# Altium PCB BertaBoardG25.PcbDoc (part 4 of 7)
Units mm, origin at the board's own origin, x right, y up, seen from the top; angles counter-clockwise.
Board outline 160 x 160 mm, 4 copper layers (Top, GND Plane, Power Plane, Bottom), stack 1.344 mm thick; 17 components, 112 nets, 2311 pads, 138 vias.
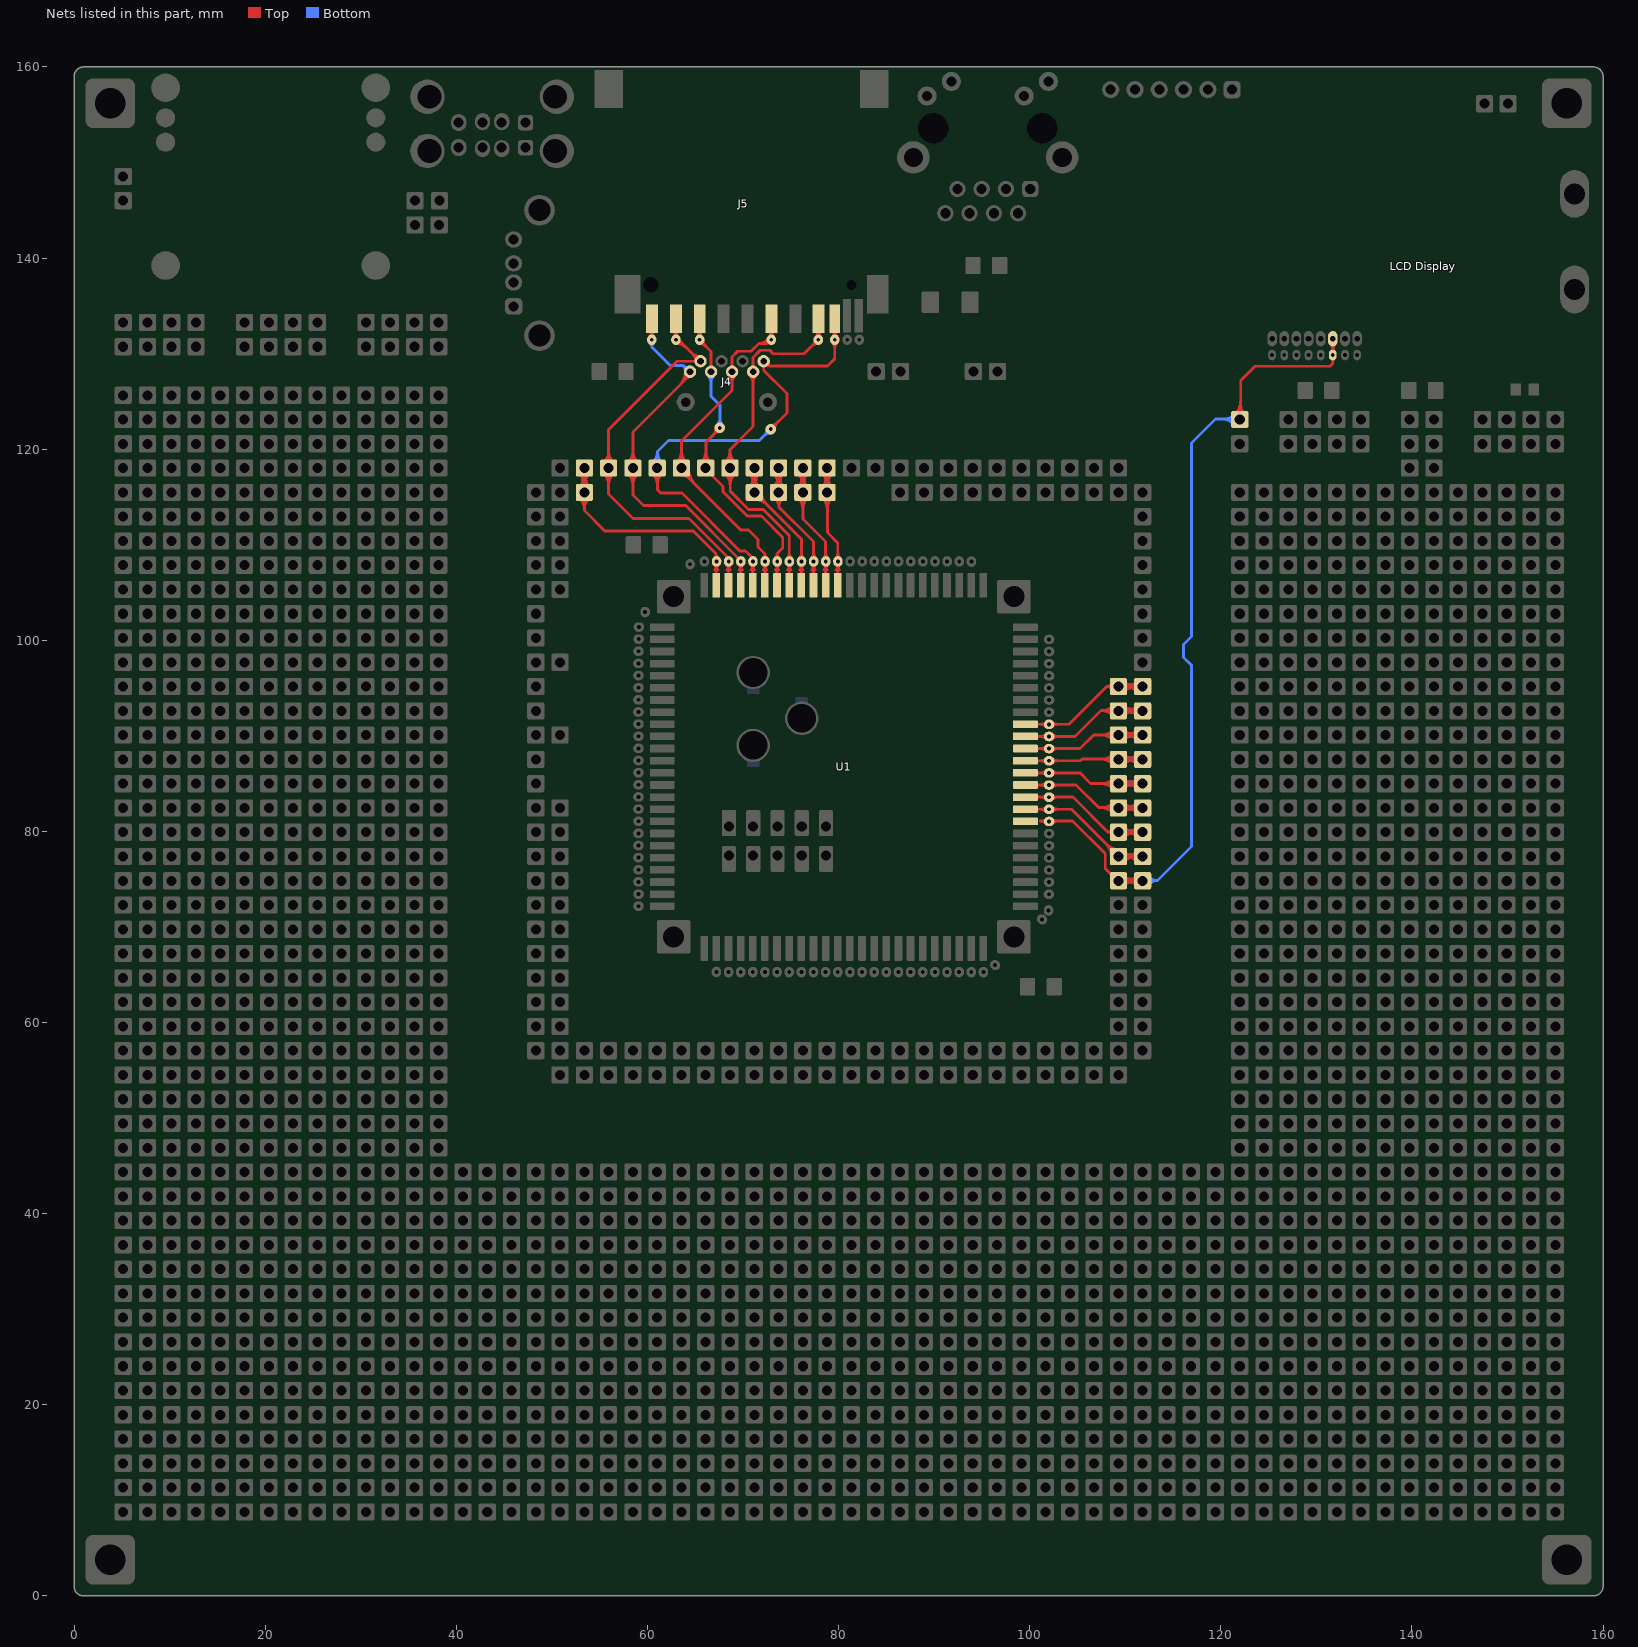
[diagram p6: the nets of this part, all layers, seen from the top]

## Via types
v1: diameter 1.5, hole 0.7, Top to Bottom, tented both sides, 54 vias
v2: diameter 1.1, hole 0.4, Top to Bottom, tented both sides, 49 vias
v3: diameter 1.9, hole 1.05, Top to Bottom, tented both sides, 17 vias
v4: diameter 1.9, hole 1.05, Top to Bottom, 16 vias
v5: diameter 0.9, hole 0.4, Top to Bottom, tented both sides, 2 vias

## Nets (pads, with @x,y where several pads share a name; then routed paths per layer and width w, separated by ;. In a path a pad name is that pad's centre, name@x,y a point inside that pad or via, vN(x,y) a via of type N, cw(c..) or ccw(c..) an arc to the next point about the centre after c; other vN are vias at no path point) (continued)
PA11: pad.0@78.802,115.48 pad.0@78.802,118.02 pad.0@79.934,108.261 U1.S12 | length 49.5
  Top w0.3: pad.0@78.271,114.949 cw(c76.92,113.598) 78.831,113.598 ; pad.0@78.271,116.01 ccw(c76.92,117.361) pad.0@78.831,117.361 ; pad.0@78.271,117.489 cw(c76.92,116.138) pad.0@78.831,116.138 ; pad.0@78.409,116.118 ccw(c78.105,116.611) 78.664,116.761 ccw(c79.626,117.019) pad.0@79.156,116.141 ; pad.0@78.434,116.134 ccw(c77.873,117.133) 78.98,116.836 ccw(c79.661,116.654) pad.0@79.245,116.085 ; pad.0@78.484,115.161 cw(c77.644,114.322) 78.831,114.322 ; pad.0@78.484,115.798 ccw(c77.644,116.637) 78.831,116.637 ; pad.0@78.484,117.701 cw(c77.644,116.862) 78.831,116.862 ; 78.831,113.74 cw(c80.541,113.74) pad.0@79.332,114.949 ; 78.831,114.464 cw(c79.817,114.464) pad.0@79.12,115.161 ; pad.0@78.831,116.28 cw(c80.541,116.28) pad.0@79.332,117.489 ; 78.831,116.495 ccw(c79.817,116.495) pad.0@79.12,115.798 ; 78.831,117.004 cw(c79.817,117.004) pad.0@79.12,117.701 ; pad.0@78.831,117.219 ccw(c80.541,117.219) pad.0@79.332,116.01 ; pad.0@78.831,118.06 78.831,111.269 79.916,110.184 U1.S12@79.916,105.77 ; 78.867,116.413 ccw(c79.383,116.274) pad.0@79.067,115.843 ; pad.0@79.686,107.963 cw(c79.131,107.408) 79.916,107.408 ; pad.0@79.686,108.558 ccw(c79.131,109.114) 79.916,109.114 ; 79.739,107.347 ccw(c79.313,107.773) 79.916,107.773 ccw(c80.52,107.773) 80.093,107.347 ; 79.916,107.324 cw(c80.821,107.324) pad.0@80.181,107.963 ; 79.916,109.198 ccw(c80.821,109.198) pad.0@80.181,108.558
  Bottom w0.3: pad.0@78.271,116.01 ccw(c76.92,117.361) pad.0@78.831,117.361 ; pad.0@78.271,117.489 cw(c76.92,116.138) pad.0@78.831,116.138 ; pad.0@78.409,116.118 ccw(c78.105,116.611) 78.664,116.761 ccw(c79.626,117.019) pad.0@79.156,116.141 ; pad.0@78.434,116.134 ccw(c77.873,117.133) 78.98,116.836 ccw(c79.661,116.654) pad.0@79.245,116.085 ; pad.0@78.484,115.798 ccw(c77.644,116.637) 78.831,116.637 ; pad.0@78.484,117.701 cw(c77.644,116.862) 78.831,116.862 ; pad.0@78.831,115.52 pad.0@78.831,118.06 ; pad.0@78.831,116.28 cw(c80.541,116.28) pad.0@79.332,117.489 ; 78.831,116.495 ccw(c79.817,116.495) pad.0@79.12,115.798 ; 78.831,117.004 cw(c79.817,117.004) pad.0@79.12,117.701 ; pad.0@78.831,117.219 ccw(c80.541,117.219) pad.0@79.332,116.01 ; 78.867,116.413 ccw(c79.383,116.274) pad.0@79.067,115.843
PA12: pad.0@76.262,115.48 pad.0@76.262,118.02 pad.0@78.664,108.261 U1.S11 | length 50.1
  Top w0.3: pad.0@75.731,114.949 cw(c74.38,113.598) 76.291,113.598 ; pad.0@75.731,116.01 ccw(c74.38,117.361) pad.0@76.291,117.361 ; pad.0@75.731,117.489 cw(c74.38,116.138) pad.0@76.291,116.138 ; pad.0@75.869,116.118 ccw(c75.565,116.611) 76.124,116.761 ccw(c77.086,117.019) pad.0@76.616,116.141 ; pad.0@75.894,116.134 ccw(c75.333,117.133) 76.44,116.836 ccw(c77.121,116.654) pad.0@76.705,116.085 ; pad.0@75.944,115.161 cw(c75.104,114.322) 76.291,114.322 ; pad.0@75.944,115.798 ccw(c75.104,116.637) 76.291,116.637 ; pad.0@75.944,117.701 cw(c75.104,116.862) 76.291,116.862 ; 76.291,113.74 cw(c78.001,113.74) pad.0@76.792,114.949 ; 76.291,114.464 cw(c77.277,114.464) pad.0@76.58,115.161 ; pad.0@76.291,116.28 cw(c78.001,116.28) pad.0@76.792,117.489 ; 76.291,116.495 ccw(c77.277,116.495) pad.0@76.58,115.798 ; 76.291,117.004 cw(c77.277,117.004) pad.0@76.58,117.701 ; pad.0@76.291,117.219 ccw(c78.001,117.219) pad.0@76.792,116.01 ; pad.0@76.291,118.06 76.291,112.709 78.646,110.354 U1.S11@78.646,105.77 ; 76.327,116.413 ccw(c76.843,116.274) pad.0@76.527,115.843 ; pad.0@78.416,107.963 cw(c77.861,107.408) 78.646,107.408 ; pad.0@78.416,108.558 ccw(c77.861,109.114) 78.646,109.114 ; 78.469,107.347 ccw(c78.043,107.773) 78.646,107.773 ccw(c79.25,107.773) 78.823,107.347 ; 78.646,107.324 cw(c79.551,107.324) pad.0@78.911,107.963 ; 78.646,109.198 ccw(c79.551,109.198) pad.0@78.911,108.558
  Bottom w0.3: pad.0@75.731,116.01 ccw(c74.38,117.361) pad.0@76.291,117.361 ; pad.0@75.731,117.489 cw(c74.38,116.138) pad.0@76.291,116.138 ; pad.0@75.869,116.118 ccw(c75.565,116.611) 76.124,116.761 ccw(c77.086,117.019) pad.0@76.616,116.141 ; pad.0@75.894,116.134 ccw(c75.333,117.133) 76.44,116.836 ccw(c77.121,116.654) pad.0@76.705,116.085 ; pad.0@75.944,115.798 ccw(c75.104,116.637) 76.291,116.637 ; pad.0@75.944,117.701 cw(c75.104,116.862) 76.291,116.862 ; pad.0@76.291,115.52 pad.0@76.291,118.06 ; pad.0@76.291,116.28 cw(c78.001,116.28) pad.0@76.792,117.489 ; 76.291,116.495 ccw(c77.277,116.495) pad.0@76.58,115.798 ; 76.291,117.004 cw(c77.277,117.004) pad.0@76.58,117.701 ; pad.0@76.291,117.219 ccw(c78.001,117.219) pad.0@76.792,116.01 ; 76.327,116.413 ccw(c76.843,116.274) pad.0@76.527,115.843
PA13: pad.0@73.722,115.48 pad.0@73.722,118.02 pad.0@77.394,108.261 U1.S10 | length 45
  Top w0.3: pad.0@73.191,116.01 ccw(c71.719,117.482) pad.0@73.801,117.482 ; pad.0@73.191,117.489 cw(c71.719,116.017) pad.0@73.801,116.017 ; pad.0@73.281,114.873 cw(c72.609,113.949) 73.751,113.949 ; pad.0@73.376,116.145 ccw(c73.154,116.572) 73.619,116.697 ccw(c74.46,116.922) pad.0@74.063,116.147 ; pad.0@73.404,115.798 ccw(c72.444,116.758) 73.801,116.758 ; pad.0@73.404,117.701 cw(c72.444,116.741) 73.801,116.741 ; pad.0@73.457,115.116 cw(c73.037,114.538) 73.751,114.538 ; pad.0@73.751,115.49 73.751,113.949 ; pad.0@73.801,115.42 pad.0@73.801,117.99 ; 73.801,116.401 cw(c75.341,116.401) pad.0@74.252,117.489 ; 73.801,117.099 ccw(c75.341,117.099) pad.0@74.252,116.01 ; pad.0@74.2,114.902 ccw(c74.987,113.949) 73.751,113.949 ; pad.0@77.146,107.963 cw(c76.591,107.408) 77.376,107.408 ; pad.0@77.146,108.558 ccw(c76.591,109.114) 77.376,109.114 ; 77.199,107.347 ccw(c76.773,107.773) 77.376,107.773 ccw(c77.98,107.773) 77.553,107.347 ; U1.S10@77.376,105.77 77.376,110.324 73.751,113.949 ; 77.376,107.324 cw(c78.281,107.324) pad.0@77.641,107.963 ; 77.376,109.198 ccw(c78.281,109.198) pad.0@77.641,108.558
  Bottom w0.3: pad.0@73.191,116.01 ccw(c71.84,117.361) pad.0@73.751,117.361 ; pad.0@73.191,117.489 cw(c71.84,116.138) pad.0@73.751,116.138 ; pad.0@73.329,116.118 ccw(c73.025,116.611) 73.584,116.761 ccw(c74.546,117.019) pad.0@74.076,116.141 ; pad.0@73.354,116.134 ccw(c72.793,117.133) 73.9,116.836 ccw(c74.581,116.654) pad.0@74.165,116.085 ; pad.0@73.404,115.798 ccw(c72.564,116.637) 73.751,116.637 ; pad.0@73.404,117.701 cw(c72.564,116.862) 73.751,116.862 ; pad.0@73.751,115.52 pad.0@73.751,118.06 ; pad.0@73.751,116.28 cw(c75.461,116.28) pad.0@74.252,117.489 ; 73.751,116.495 ccw(c74.737,116.495) pad.0@74.04,115.798 ; 73.751,117.004 cw(c74.737,117.004) pad.0@74.04,117.701 ; pad.0@73.751,117.219 ccw(c75.461,117.219) pad.0@74.252,116.01 ; 73.787,116.413 ccw(c74.303,116.274) pad.0@73.987,115.843
PA14: pad.0@71.182,115.48 pad.0@71.182,118.02 pad.0@76.124,108.261 U1.S9 | length 51.1
  Top w0.3: pad.0@70.651,116.01 ccw(c69.3,117.361) pad.0@71.211,117.361 ; pad.0@70.651,117.489 cw(c69.3,116.138) pad.0@71.211,116.138 ; pad.0@70.789,116.118 ccw(c70.485,116.611) 71.044,116.761 ccw(c72.006,117.019) pad.0@71.536,116.141 ; pad.0@70.814,116.134 ccw(c70.253,117.133) 71.36,116.836 ccw(c72.041,116.654) pad.0@71.625,116.085 ; pad.0@70.864,115.798 ccw(c70.024,116.637) 71.211,116.637 ; pad.0@70.864,117.701 cw(c70.024,116.862) 71.211,116.862 ; pad.0@71.182,114.73 cw(c71.182,112.775) 72.564,114.157 ; pad.0@71.182,115.03 cw(c71.182,113.799) pad.0@72.052,114.669 ; pad.0@71.211,115.289 71.432,115.289 76.106,110.615 U1.S9@76.106,105.77 ; pad.0@71.211,115.49 pad.0@71.211,118.06 ; pad.0@71.211,116.28 cw(c72.921,116.28) pad.0@71.712,117.489 ; 71.211,116.495 ccw(c72.197,116.495) pad.0@71.5,115.798 ; 71.211,117.004 cw(c72.197,117.004) pad.0@71.5,117.701 ; pad.0@71.211,117.219 ccw(c72.921,117.219) pad.0@71.712,116.01 ; 71.247,116.413 ccw(c71.763,116.274) pad.0@71.447,115.843 ; pad.0@71.632,115.48 ccw(c72.574,115.48) pad.0@71.908,114.813 ; pad.0@71.932,115.48 ccw(c73.599,115.48) 72.42,114.301 ; pad.0@75.876,107.963 cw(c75.321,107.408) 76.106,107.408 ; pad.0@75.876,108.558 ccw(c75.321,109.114) 76.106,109.114 ; 75.929,107.347 ccw(c75.503,107.773) 76.106,107.773 ccw(c76.71,107.773) 76.283,107.347 ; 76.106,107.324 cw(c77.011,107.324) pad.0@76.371,107.963 ; 76.106,109.198 ccw(c77.011,109.198) pad.0@76.371,108.558
  Bottom w0.3: pad.0@70.651,116.01 ccw(c69.3,117.361) pad.0@71.211,117.361 ; pad.0@70.651,117.489 cw(c69.3,116.138) pad.0@71.211,116.138 ; pad.0@70.789,116.118 ccw(c70.485,116.611) 71.044,116.761 ccw(c72.006,117.019) pad.0@71.536,116.141 ; pad.0@70.814,116.134 ccw(c70.253,117.133) 71.36,116.836 ccw(c72.041,116.654) pad.0@71.625,116.085 ; pad.0@70.864,115.798 ccw(c70.024,116.637) 71.211,116.637 ; pad.0@70.864,117.701 cw(c70.024,116.862) 71.211,116.862 ; pad.0@71.211,115.52 pad.0@71.211,118.06 ; pad.0@71.211,116.28 cw(c72.921,116.28) pad.0@71.712,117.489 ; 71.211,116.495 ccw(c72.197,116.495) pad.0@71.5,115.798 ; 71.211,117.004 cw(c72.197,117.004) pad.0@71.5,117.701 ; pad.0@71.211,117.219 ccw(c72.921,117.219) pad.0@71.712,116.01 ; 71.247,116.413 ccw(c71.763,116.274) pad.0@71.447,115.843
PA15: J4.7 J5.7 pad.0@68.642,118.02 pad.0@74.854,108.261 pad.0@77.884,131.451 U1.S8 | length 57.5
  Top w0.3: pad.0@68.111,117.489 cw(c66.76,116.138) 68.671,116.138 ; pad.0@68.111,118.55 ccw(c66.832,119.829) 68.641,119.829 ; pad.0@68.324,117.701 cw(c67.484,116.862) 68.671,116.862 ; pad.0@68.324,118.338 ccw(c67.557,119.105) 68.641,119.105 ; pad.0@68.641,117.9 68.641,119.94 71.058,122.358 J4.7@71.058,128.103 71.058,129.597 71.811,130.35 72.8,130.35 73.17,129.98 76.391,129.98 pad.0@77.901,131.489 ; 68.641,119.107 ccw(c69.73,119.107) pad.0@68.96,118.338 ; 68.641,119.832 ccw(c70.454,119.832) pad.0@69.172,118.55 ; 68.671,116.28 cw(c70.381,116.28) pad.0@69.172,117.489 ; 68.671,117.004 cw(c69.657,117.004) pad.0@68.96,117.701 ; pad.0@68.671,118.03 68.671,115.602 70.574,113.7 72.121,113.7 74.836,110.985 U1.S8@74.836,105.77 ; J4.7@70.705,127.75 cw(c69.851,126.896) 71.058,126.896 cw(c72.266,126.896) J4.7@71.412,127.75 ; pad.0@74.606,107.963 cw(c74.051,107.408) 74.836,107.408 ; pad.0@74.606,108.558 ccw(c74.051,109.114) 74.836,109.114 ; 74.659,107.347 ccw(c74.233,107.773) 74.836,107.773 ccw(c75.44,107.773) 75.013,107.347 ; 74.836,107.324 cw(c75.741,107.324) pad.0@75.101,107.963 ; 74.836,109.198 ccw(c75.741,109.198) pad.0@75.101,108.558 ; 77.165,130.753 cw(c77.884,130.034) pad.0@77.884,131.051 ; 77.336,130.925 ccw(c76.86,131.401) pad.0@77.534,131.401
  Top w0.35: J5.7@77.584,132.46 cw(c76.82,131.695) pad.0@77.901,131.695 ; pad.0@77.654,131.731 ccw(c77.058,132.327) J5.7@77.901,132.327 ; J5.7@77.712,132.37 cw(c77.614,132.158) 77.839,132.098 cw(c78.219,131.996) J5.7@78.071,132.361 ; J5.7@77.72,132.366 cw(c77.565,132.015) 77.935,132.115 cw(c78.131,132.167) J5.7@78.06,132.356 ; pad.0@77.901,131.489 J5.7@77.901,132.4 ; pad.0@77.901,131.688 cw(c78.992,131.688) J5.7@78.22,132.46 ; J5.7@77.901,132.244 ccw(c78.627,132.244) pad.0@78.113,131.731
PA16: J4.3 J5.2@65.477,133.653 pad.0@65.464,131.451 pad.0@66.102,118.02 pad.0@73.584,108.261 U1.S7 | length 52.1
  Top w0.3: J5.2@65.141,132.442 cw(c64.33,131.631) 65.477,131.631 cw(c66.624,131.631) J5.2@65.813,132.442 ; pad.0@65.216,131.748 ccw(c64.586,132.379) J5.2@65.477,132.379 ; J5.2@65.29,132.341 cw(c65.211,132.158) 65.404,132.106 cw(c65.704,132.025) J5.2@65.614,132.323 ; J5.2@65.33,132.326 cw(c65.236,132.036) 65.53,132.115 cw(c65.706,132.162) J5.2@65.642,132.332 ; pad.0@65.464,131.051 cw(c65.464,130.142) 66.106,130.785 ; J5.2@65.477,132.313 ccw(c66.276,132.313) pad.0@65.711,131.748 ; J5.2@65.477,133.653 65.477,131.414 66.658,130.232 J4.3@66.658,128.603 ; pad.0@65.571,118.55 ccw(c64.22,119.901) 66.131,119.901 ; pad.0@65.784,118.338 ccw(c64.944,119.177) 66.131,119.177 ; pad.0@65.814,131.401 ccw(c66.595,131.401) 66.042,130.848 ; pad.0@66.131,117.869 67.901,116.1 67.901,115.539 70.439,113 71.921,113 74.161,110.76 74.161,109.66 73.566,109.065 ; pad.0@66.131,118.03 66.131,120.73 v2@67.601,122.2 ; 66.131,119.035 ccw(c67.117,119.035) pad.0@66.42,118.338 ; 66.131,119.759 ccw(c67.841,119.759) pad.0@66.632,118.55 ; 66.857,121.457 ccw(c66.089,122.225) v2@67.176,122.225 ; 66.978,121.577 cw(c67.576,120.98) v2@67.576,121.825 ; pad.0@73.336,107.963 cw(c72.781,107.408) 73.566,107.408 ; pad.0@73.348,108.569 ccw(c72.896,109.065) 73.566,109.065 ; 73.389,107.347 ccw(c72.963,107.773) 73.566,107.773 ccw(c74.17,107.773) 73.743,107.347 ; U1.S7@73.566,105.77 73.566,109.065 ; 73.566,107.324 cw(c74.471,107.324) pad.0@73.831,107.963 ; pad.0@73.799,108.587 cw(c74.173,109.065) 73.566,109.065
  Bottom w0.3: J4.3@66.305,127.75 cw(c65.451,126.896) 66.658,126.896 cw(c67.866,126.896) J4.3@67.012,127.75 ; J4.3@66.658,128.603 J4.3@66.658,128.103 66.658,125.542 67.601,124.6 v2@67.601,122.225 ; v2@67.293,122.508 ccw(c66.55,123.251) 67.601,123.251 ; 67.601,123.13 ccw(c68.481,123.13) v2@67.858,122.508
  other v2: 67.576,122.225
PA17: J4.5 J5.5 pad.0@63.562,118.02 pad.0@72.314,108.261 pad.0@72.964,131.451 U1.S6 | length 57.5
  Top w0.3: pad.0@63.031,118.55 ccw(c61.752,119.829) 63.561,119.829 ; pad.0@63.244,118.338 ccw(c62.477,119.105) 63.561,119.105 ; pad.0@63.561,118.03 63.561,120.86 68.858,126.158 J4.5@68.858,128.103 68.858,129.658 69.45,130.25 70.85,130.25 71.67,131.07 72.521,131.07 ; 63.561,119.107 ccw(c64.65,119.107) pad.0@63.88,118.338 ; 63.561,119.832 ccw(c65.374,119.832) pad.0@64.092,118.55 ; pad.0@63.562,117.27 cw(c63.562,116.088) 64.397,116.923 ; pad.0@63.591,118.06 63.591,117.73 69.761,111.56 70.561,111.56 71.561,110.56 71.561,109.76 72.296,109.025 ; pad.0@64.012,118.02 ccw(c65.727,118.02) 64.514,116.807 ; pad.0@64.312,118.02 ccw(c66.751,118.02) 65.026,116.295 ; J4.5@68.505,127.75 cw(c67.651,126.896) 68.858,126.896 cw(c70.066,126.896) J4.5@69.212,127.75 ; 71.67,131.07 ccw(c71.67,132.288) pad.0@72.675,131.599 ; pad.0@72.066,107.963 cw(c71.511,107.408) 72.296,107.408 ; pad.0@72.088,108.579 ccw(c71.714,109.025) 72.296,109.025 ; 72.119,107.347 ccw(c71.693,107.773) 72.296,107.773 ccw(c72.9,107.773) 72.473,107.347 ; 72.24,131.07 ccw(c72.24,131.897) pad.0@72.922,131.429 ; U1.S6@72.296,105.77 72.296,109.025 ; 72.296,107.324 cw(c73.201,107.324) pad.0@72.561,107.963 ; pad.0@72.517,108.596 cw(c72.823,109.025) 72.296,109.025 ; pad.0@72.617,131.354 cw(c72.283,131.308) 72.521,131.07 ; J5.5@72.641,132.442 cw(c71.893,131.694) pad.0@72.951,131.694 ; pad.0@72.716,131.748 ccw(c72.149,132.316) J5.5@72.951,132.316 ; J5.5@72.761,132.355 cw(c72.649,132.136) 72.886,132.073 cw(c73.241,131.977) J5.5@73.126,132.327 ; pad.0@72.782,131.101 ccw(c72.672,130.919) 72.521,131.07 ; pad.0@72.951,131.568 cw(c74.187,131.568) J5.5@73.313,132.442 ; J5.5@72.977,133.653 72.977,132.376 J5.5@72.951,132.35 ; pad.0@73.206,131.754 cw(c73.778,132.35) J5.5@72.951,132.35 ; 72.521,131.07 72.951,131.5 J5.5@72.951,132.35
PA18: J4.8 J5.8 pad.0@61.022,118.02 pad.0@71.044,108.261 pad.0@79.604,131.451 U1.S5 | length 74.8
  Top w0.3: pad.0@60.491,117.489 cw(c59.14,116.138) 61.051,116.138 ; pad.0@60.704,117.701 cw(c59.864,116.862) 61.051,116.862 ; 61.051,116.28 cw(c62.761,116.28) pad.0@61.552,117.489 ; 61.051,117.004 cw(c62.037,117.004) pad.0@61.34,117.701 ; pad.0@61.051,118.03 61.051,115.749 61.4,115.401 63.62,115.401 69.661,109.36 70.261,109.36 70.861,108.76 70.861,108.039 71.026,107.874 U1.S5@71.026,105.77 ; pad.0@61.071,118.06 pad.0@61.111,118.4 ; pad.0@70.796,107.963 cw(c70.241,107.408) 71.026,107.408 ; 70.849,107.347 ccw(c70.423,107.773) 71.026,107.773 ccw(c71.63,107.773) 71.203,107.347 ; 71.026,107.324 cw(c71.931,107.324) pad.0@71.291,107.963 ; J4.8@72.158,129.703 72.158,129.322 72.781,128.7 ; J4.8@72.171,129.19 72.171,128.24 74.601,125.81 74.601,123.8 v2(72.901,122.1) ; J4.8@72.39,128.76 cw(c72.544,128.463) 72.781,128.7 ; J4.8@72.651,129.115 ccw(c73.114,129.032) 72.781,128.7 ; v2@72.901,122.5 ccw(c72.901,123.466) 73.583,122.783 ccw(c74.266,122.1) v2@73.301,122.1 ; J5.8@79.319,132.42 cw(c78.636,131.737) 79.602,131.737 cw(c80.568,131.737) J5.8@79.885,132.42 ; pad.0@79.356,131.153 cw(c78.762,130.559) 79.602,130.559 ; pad.0@79.356,131.748 ccw(c78.762,132.343) J5.8@79.602,132.343 ; J5.8@79.414,132.35 cw(c79.301,132.14) 79.531,132.078 cw(c79.901,131.979) J5.8@79.755,132.333 ; J5.8@79.45,132.333 cw(c79.305,131.978) 79.675,132.077 cw(c79.907,132.14) J5.8@79.793,132.351 ; 79.602,130.553 cw(c80.452,130.553) pad.0@79.851,131.153 ; J5.8@79.602,132.349 ccw(c80.452,132.349) pad.0@79.851,131.748 ; J5.8@79.602,133.653 79.602,129.471 78.831,128.7 72.781,128.7
  Bottom w0.3: pad.0@60.525,118.581 ccw(c59.49,119.75) 61.051,119.75 ; pad.0@60.723,118.357 ccw(c60.079,119.084) 61.051,119.084 ; pad.0@61.051,118.03 61.051,118.06 61.051,119.75 ; 61.051,119.03 ccw(c62.025,119.03) pad.0@61.339,118.339 ; pad.0@61.55,118.552 cw(c62.74,119.75) 61.051,119.75 ; v2@72.501,122.1 cw(c71.535,122.1) 72.218,121.417 cw(c72.901,120.734) v2@72.901,121.7 ; v2(72.901,122.1) 71.701,120.9 62.201,120.9 61.051,119.75
PA19: J4.1 J5.9 pad.0@58.482,118.02 pad.0@60.454,131.451 pad.0@69.774,108.261 U1.S4 | length 60.6
  Top w0.3: pad.0@57.951,117.489 cw(c56.672,116.21) 58.481,116.21 ; pad.0@57.951,118.55 ccw(c56.672,119.829) 58.481,119.829 ; pad.0@58.164,117.701 cw(c57.397,116.935) 58.481,116.935 ; pad.0@58.164,118.338 ccw(c57.397,119.105) 58.481,119.105 ; 58.481,116.208 cw(c60.294,116.208) pad.0@59.012,117.489 ; 58.481,116.932 cw(c59.57,116.932) pad.0@58.8,117.701 ; 58.481,119.107 ccw(c59.57,119.107) pad.0@58.8,118.338 ; 58.481,119.832 ccw(c60.294,119.832) pad.0@59.012,118.55 ; J5.9@60.162,132.422 cw(c59.544,131.723) pad.0@60.477,131.723 ; pad.0@60.206,131.748 ccw(c59.552,132.403) J5.9@60.477,132.403 ; J5.9@60.282,132.345 cw(c60.197,132.156) 60.397,132.102 cw(c60.699,132.021) J5.9@60.611,132.322 ; J5.9@60.326,132.327 cw(c60.23,132.04) 60.523,132.118 cw(c60.692,132.164) J5.9@60.634,132.329 ; J5.9@60.477,132.289 ccw(c61.242,132.289) pad.0@60.701,131.748 ; J5.9@60.477,133.653 pad.0@60.477,131.723 ; J5.9@60.792,132.422 ccw(c61.41,131.723) pad.0@60.477,131.723 ; 63.367,126.676 ccw(c61.939,128.103) J4.1@63.958,128.103 ; 63.879,127.188 ccw(c62.964,128.103) J4.1@64.258,128.103 ; 64.179,127.488 cw(c64.458,127.208) J4.1@64.458,127.603 ; J4.1@64.458,128.003 64.458,127.767 58.481,121.79 58.481,115.219 59.595,114.106 64.015,114.106 69.756,108.365 U1.S4@69.756,105.77 ; pad.0@69.526,107.963 cw(c68.971,107.408) 69.756,107.408 ; 69.579,107.347 ccw(c69.153,107.773) 69.756,107.773 ccw(c70.36,107.773) 69.933,107.347 ; 69.756,107.324 cw(c70.661,107.324) pad.0@70.021,107.963
  Bottom w0.3: pad.0@60.239,131.124 cw(c59.901,130.687) 60.454,130.687 ; pad.0@60.454,131.451 60.454,130.687 ; pad.0@60.668,131.124 ccw(c61.006,130.687) 60.454,130.687 ; J4.1@63.959,128.133 ccw(c63.143,128.181) 63.721,128.76 ; J4.1@64.228,128.103 J4.1@64.458,128.103 J4.1@64.458,128.003 ; J4.1@64.258,128.223 63.721,128.76 ; J4.1@64.338,128.589 cw(c64.181,129.219) 63.721,128.76 ; 60.454,130.687 62.381,128.76 63.721,128.76
PA20: J4.2 J5.1@62.977,133.653 pad.0@55.942,118.02 pad.0@62.984,131.451 pad.0@68.504,108.261 U1.S3 | length 60.5
  Top w0.3: pad.0@55.411,117.489 cw(c54.132,116.21) 55.941,116.21 ; pad.0@55.411,118.55 ccw(c54.132,119.829) 55.941,119.829 ; pad.0@55.624,117.701 cw(c54.857,116.935) 55.941,116.935 ; pad.0@55.624,118.338 ccw(c54.857,119.105) 55.941,119.105 ; 55.941,116.208 cw(c57.754,116.208) pad.0@56.472,117.489 ; 55.941,116.932 cw(c57.03,116.932) pad.0@56.26,117.701 ; 55.941,119.107 ccw(c57.03,119.107) pad.0@56.26,118.338 ; 55.941,119.832 ccw(c57.754,119.832) pad.0@56.472,118.55 ; J5.1@62.662,132.422 cw(c62.044,131.723) pad.0@62.977,131.723 ; pad.0@62.736,131.748 ccw(c62.154,132.33) J5.1@62.977,132.33 ; J5.1@62.806,132.335 cw(c62.739,132.161) 62.919,132.113 cw(c63.215,132.033) J5.1@63.122,132.325 ; J5.1@62.837,132.324 cw(c62.746,132.028) 63.045,132.108 cw(c63.233,132.159) J5.1@63.159,132.339 ; J5.1@62.977,132.361 ccw(c63.844,132.361) pad.0@63.231,131.748 ; J5.1@62.977,133.653 pad.0@62.977,131.723 ; pad.0@62.984,131.051 cw(c62.984,129.443) 64.12,130.58 ; pad.0@62.984,131.351 cw(c62.984,130.467) 63.608,131.092 ; J5.1@63.292,132.422 ccw(c63.91,131.723) pad.0@62.977,131.723 ; 64.6,130.1 ccw(c65.558,131.058) J4.2@65.558,129.703 ; 64.748,129.952 cw(c63.999,129.203) J4.2@65.058,129.203 ; J4.2@65.055,129.2 63.101,129.2 55.941,122.04 55.941,115.32 58.502,112.759 64.362,112.759 68.501,108.62 68.501,107.2 ; J4.2@65.578,129.123 pad.0@62.977,131.723 ; pad.0@68.256,107.963 cw(c67.666,107.373) 68.501,107.373 ; 68.309,107.347 ccw(c67.848,107.808) pad.0@68.501,107.808 ; 68.501,107.359 cw(c69.356,107.359) pad.0@68.751,107.963 ; pad.0@68.501,107.738 ccw(c69.055,107.738) 68.663,107.347
PA21: pad.0@53.402,115.48 pad.0@53.402,118.02 pad.0@67.234,108.261 U1.S2 | length 59.7
  Top w0.3: pad.0@52.871,114.949 cw(c51.592,113.67) 53.401,113.67 ; pad.0@52.871,116.01 ccw(c51.592,117.289) pad.0@53.401,117.289 ; pad.0@52.871,117.489 cw(c51.592,116.21) pad.0@53.401,116.21 ; pad.0@52.982,117.398 cw(c52.624,116.866) 53.243,116.7 cw(c54.279,116.423) pad.0@53.763,117.362 ; pad.0@53.041,117.362 cw(c52.527,116.425) 53.559,116.702 cw(c54.176,116.867) pad.0@53.82,117.397 ; pad.0@53.084,115.161 cw(c52.317,114.395) 53.401,114.395 ; pad.0@53.084,115.798 ccw(c52.317,116.565) 53.401,116.565 ; pad.0@53.084,117.701 cw(c52.317,116.935) 53.401,116.935 ; pad.0@53.15,117.646 cw(c52.873,117.235) 53.352,117.106 ; 53.401,113.668 cw(c55.214,113.668) pad.0@53.932,114.949 ; 53.401,114.392 cw(c54.49,114.392) pad.0@53.72,115.161 ; pad.0@53.401,116.208 cw(c55.214,116.208) pad.0@53.932,117.489 ; 53.401,116.567 ccw(c54.49,116.567) pad.0@53.72,115.798 ; 53.401,116.932 cw(c54.49,116.932) pad.0@53.72,117.701 ; pad.0@53.401,117.292 ccw(c55.214,117.292) pad.0@53.932,116.01 ; pad.0@53.401,118.06 53.401,113.57 55.541,111.43 64.791,111.43 67.201,109.02 ; 53.451,117.107 cw(c53.929,117.235) pad.0@53.653,117.646 ; pad.0@66.986,107.963 cw(c66.468,107.446) 67.201,107.446 ; pad.0@67,108.572 ccw(c66.599,109.02) 67.201,109.02 ; 67.039,107.347 ccw(c66.65,107.736) pad.0@67.201,107.736 ; 67.201,107.2 67.201,109.02 ; 67.201,107.286 cw(c68.158,107.286) pad.0@67.481,107.963 ; pad.0@67.201,107.811 ccw(c67.857,107.811) 67.393,107.347 ; pad.0@67.426,108.604 cw(c67.699,109.02) 67.201,109.02
  Bottom w0.3: pad.0@52.871,116.01 ccw(c51.592,117.289) pad.0@53.401,117.289 ; pad.0@52.871,117.489 cw(c51.592,116.21) pad.0@53.401,116.21 ; pad.0@52.982,117.398 cw(c52.624,116.866) 53.243,116.7 cw(c54.279,116.423) pad.0@53.763,117.362 ; pad.0@53.041,117.362 cw(c52.527,116.425) 53.559,116.702 cw(c54.176,116.867) pad.0@53.82,117.397 ; pad.0@53.084,115.798 ccw(c52.317,116.565) 53.401,116.565 ; pad.0@53.084,117.701 cw(c52.317,116.935) 53.401,116.935 ; pad.0@53.15,117.646 cw(c52.873,117.235) 53.352,117.106 ; pad.0@53.401,115.52 pad.0@53.401,118.06 ; pad.0@53.401,116.208 cw(c55.214,116.208) pad.0@53.932,117.489 ; 53.401,116.567 ccw(c54.49,116.567) pad.0@53.72,115.798 ; 53.401,116.932 cw(c54.49,116.932) pad.0@53.72,117.701 ; pad.0@53.401,117.292 ccw(c55.214,117.292) pad.0@53.932,116.01 ; 53.451,117.107 cw(c53.929,117.235) pad.0@53.653,117.646
PA22: pad.0@102.032,91.207 pad.0@109.282,95.16 pad.0@111.822,95.16 U1.W9 | length 47.3
  Top w0.3: U1.W9@99.551,91.215 104.116,91.215 108.091,95.19 ; U1.W9@99.992,91.255 ccw(c100.089,91.353) U1.W9@100.089,91.215 ; U1.W9@100.204,91.467 ccw(c100.813,92.077) U1.W9@100.813,91.215 ; 101.119,91.215 cw(c101.119,90.344) pad.0@101.735,90.96 ; 101.155,91.215 ccw(c101.155,92.034) pad.0@101.735,91.455 ; pad.0@102.33,90.96 cw(c102.945,90.344) 102.945,91.215 ; pad.0@102.33,91.455 ccw(c102.909,92.034) 102.909,91.215 ; pad.0@108.594,94.86 ccw(c108.091,94.641) 108.091,95.19 ; pad.0@108.618,95.508 cw(c108.091,95.784) 108.091,95.19 ; pad.0@109.6,94.841 cw(c110.441,94) 110.441,95.19 ; pad.0@109.6,95.478 ccw(c110.295,96.173) 110.295,95.19 ; pad.0@109.812,94.629 cw(c111.165,93.276) pad.0@111.165,95.19 ; pad.0@109.812,95.69 ccw(c111.02,96.897) pad.0@111.02,95.19 ; pad.0@109.938,95.19 cw(c109.938,93.276) pad.0@111.291,94.629 ; pad.0@110.084,95.19 ccw(c110.084,96.897) pad.0@111.291,95.69 ; 110.663,95.19 cw(c110.663,94) pad.0@111.504,94.841 ; 110.808,95.19 ccw(c110.808,96.173) pad.0@111.504,95.478 ; 110.888,95.225 ccw(c111.027,95.743) pad.0@111.459,95.426 ; pad.0@111.161,95.514 cw(c110.284,95.983) 110.541,95.023 cw(c110.691,94.465) pad.0@111.183,94.767 ; pad.0@111.168,94.792 ccw(c110.167,94.23) 110.464,95.338 ccw(c110.647,96.021) pad.0@111.217,95.603 ; pad.0@111.861,95.19 108.091,95.19
  Bottom w0.3: pad.0@109.291,95.19 pad.0@111.831,95.19 ; pad.0@109.6,94.841 cw(c110.441,94) 110.441,95.19 ; pad.0@109.6,95.478 ccw(c110.295,96.173) 110.295,95.19 ; pad.0@109.812,94.629 cw(c111.165,93.276) pad.0@111.165,95.19 ; pad.0@109.812,95.69 ccw(c111.02,96.897) pad.0@111.02,95.19 ; pad.0@109.938,95.19 cw(c109.938,93.276) pad.0@111.291,94.629 ; pad.0@110.084,95.19 ccw(c110.084,96.897) pad.0@111.291,95.69 ; 110.663,95.19 cw(c110.663,94) pad.0@111.504,94.841 ; 110.808,95.19 ccw(c110.808,96.173) pad.0@111.504,95.478 ; 110.888,95.225 ccw(c111.027,95.743) pad.0@111.459,95.426 ; pad.0@111.161,95.514 cw(c110.284,95.983) 110.541,95.023 cw(c110.691,94.465) pad.0@111.183,94.767 ; pad.0@111.168,94.792 ccw(c110.167,94.23) 110.464,95.338 ccw(c110.647,96.021) pad.0@111.217,95.603
PA23: pad.0@102.032,89.937 pad.0@109.282,92.62 pad.0@111.822,92.62 U1.W10 | length 50
  Top w0.3: U1.W10@99.551,89.945 104.746,89.945 107.451,92.65 ; U1.W10@99.992,89.985 ccw(c100.089,90.083) U1.W10@100.089,89.945 ; U1.W10@100.204,90.197 ccw(c100.813,90.807) U1.W10@100.813,89.945 ; 101.119,89.945 cw(c101.119,89.074) pad.0@101.735,89.69 ; 101.155,89.945 ccw(c101.155,90.764) pad.0@101.735,90.185 ; pad.0@102.33,89.69 cw(c102.945,89.074) 102.945,89.945 ; pad.0@102.33,90.185 ccw(c102.909,90.764) 102.909,89.945 ; 107.544,92.65 ccw(c107.544,94.357) pad.0@108.751,93.15 ; 108.155,92.65 cw(c108.155,91.538) pad.0@108.957,92.308 ; 108.268,92.65 ccw(c108.268,93.633) pad.0@108.964,92.938 ; pad.0@108.741,92.1 ccw(c107.451,90.862) 107.451,92.65 ; pad.0@109.6,92.301 cw(c110.441,91.46) 110.441,92.65 ; pad.0@109.6,92.938 ccw(c110.295,93.633) 110.295,92.65 ; pad.0@109.812,92.089 cw(c111.165,90.736) pad.0@111.165,92.65 ; pad.0@109.812,93.15 ccw(c111.02,94.357) pad.0@111.02,92.65 ; pad.0@109.938,92.65 cw(c109.938,90.736) pad.0@111.291,92.089 ; pad.0@110.084,92.65 ccw(c110.084,94.357) pad.0@111.291,93.15 ; 110.663,92.65 cw(c110.663,91.46) pad.0@111.504,92.301 ; 110.808,92.65 ccw(c110.808,93.633) pad.0@111.504,92.938 ; 110.888,92.685 ccw(c111.027,93.203) pad.0@111.459,92.886 ; pad.0@111.161,92.974 cw(c110.284,93.443) 110.541,92.483 cw(c110.691,91.925) pad.0@111.183,92.227 ; pad.0@111.168,92.252 ccw(c110.167,91.69) 110.464,92.798 ccw(c110.647,93.481) pad.0@111.217,93.063 ; pad.0@111.861,92.65 107.451,92.65
  Bottom w0.3: pad.0@109.291,92.65 pad.0@111.831,92.65 ; pad.0@109.6,92.301 cw(c110.441,91.46) 110.441,92.65 ; pad.0@109.6,92.938 ccw(c110.295,93.633) 110.295,92.65 ; pad.0@109.812,92.089 cw(c111.165,90.736) pad.0@111.165,92.65 ; pad.0@109.812,93.15 ccw(c111.02,94.357) pad.0@111.02,92.65 ; pad.0@109.938,92.65 cw(c109.938,90.736) pad.0@111.291,92.089 ; pad.0@110.084,92.65 ccw(c110.084,94.357) pad.0@111.291,93.15 ; 110.663,92.65 cw(c110.663,91.46) pad.0@111.504,92.301 ; 110.808,92.65 ccw(c110.808,93.633) pad.0@111.504,92.938 ; 110.888,92.685 ccw(c111.027,93.203) pad.0@111.459,92.886 ; pad.0@111.161,92.974 cw(c110.284,93.443) 110.541,92.483 cw(c110.691,91.925) pad.0@111.183,92.227 ; pad.0@111.168,92.252 ccw(c110.167,91.69) 110.464,92.798 ccw(c110.647,93.481) pad.0@111.217,93.063
PA24: pad.0@102.032,88.667 pad.0@109.282,90.08 pad.0@111.822,90.08 U1.W11 | length 49.6
  Top w0.3: U1.W11@99.551,88.675 105.275,88.675 106.71,90.11 pad.0@111.861,90.11 ; U1.W11@99.992,88.715 ccw(c100.089,88.813) U1.W11@100.089,88.675 ; U1.W11@100.204,88.927 ccw(c100.813,89.537) U1.W11@100.813,88.675 ; 101.119,88.675 cw(c101.119,87.804) pad.0@101.735,88.42 ; 101.155,88.675 ccw(c101.155,89.494) pad.0@101.735,88.915 ; pad.0@102.33,88.42 cw(c102.945,87.804) 102.945,88.675 ; pad.0@102.33,88.915 ccw(c102.909,89.494) 102.909,88.675 ; 107.398,90.11 cw(c107.398,88.196) pad.0@108.751,89.549 ; 107.544,90.11 ccw(c107.544,91.817) pad.0@108.751,90.61 ; 108.123,90.11 cw(c108.123,88.92) pad.0@108.964,89.761 ; 108.268,90.11 ccw(c108.268,91.093) pad.0@108.964,90.398 ; pad.0@109.6,89.761 cw(c110.441,88.92) 110.441,90.11 ; pad.0@109.6,90.398 ccw(c110.295,91.093) 110.295,90.11 ; pad.0@109.812,89.549 cw(c111.165,88.196) pad.0@111.165,90.11 ; pad.0@109.812,90.61 ccw(c111.02,91.817) pad.0@111.02,90.11 ; pad.0@109.938,90.11 cw(c109.938,88.196) pad.0@111.291,89.549 ; pad.0@110.084,90.11 ccw(c110.084,91.817) pad.0@111.291,90.61 ; 110.663,90.11 cw(c110.663,88.92) pad.0@111.504,89.761 ; 110.808,90.11 ccw(c110.808,91.093) pad.0@111.504,90.398 ; 110.888,90.145 ccw(c111.027,90.663) pad.0@111.459,90.346 ; pad.0@111.161,90.434 cw(c110.284,90.903) 110.541,89.943 cw(c110.691,89.385) pad.0@111.183,89.687 ; pad.0@111.168,89.712 ccw(c110.167,89.15) 110.464,90.258 ccw(c110.647,90.941) pad.0@111.217,90.523
  Bottom w0.3: pad.0@109.291,90.11 pad.0@111.831,90.11 ; pad.0@109.6,89.761 cw(c110.441,88.92) 110.441,90.11 ; pad.0@109.6,90.398 ccw(c110.295,91.093) 110.295,90.11 ; pad.0@109.812,89.549 cw(c111.165,88.196) pad.0@111.165,90.11 ; pad.0@109.812,90.61 ccw(c111.02,91.817) pad.0@111.02,90.11 ; pad.0@109.938,90.11 cw(c109.938,88.196) pad.0@111.291,89.549 ; pad.0@110.084,90.11 ccw(c110.084,91.817) pad.0@111.291,90.61 ; 110.663,90.11 cw(c110.663,88.92) pad.0@111.504,89.761 ; 110.808,90.11 ccw(c110.808,91.093) pad.0@111.504,90.398 ; 110.888,90.145 ccw(c111.027,90.663) pad.0@111.459,90.346 ; pad.0@111.161,90.434 cw(c110.284,90.903) 110.541,89.943 cw(c110.691,89.385) pad.0@111.183,89.687 ; pad.0@111.168,89.712 ccw(c110.167,89.15) 110.464,90.258 ccw(c110.647,90.941) pad.0@111.217,90.523
PA25: pad.0@102.032,87.397 pad.0@109.282,87.54 pad.0@111.822,87.54 U1.W12 | length 49
  Top w0.3: U1.W12@99.551,87.405 99.556,87.4 105.301,87.4 105.47,87.57 pad.0@111.831,87.57 ; U1.W12@99.992,87.445 ccw(c100.101,87.554) U1.W12@100.101,87.4 ; U1.W12@100.204,87.657 ccw(c100.825,88.279) U1.W12@100.825,87.4 ; 101.131,87.4 cw(c101.131,86.546) pad.0@101.735,87.15 ; 101.143,87.4 ccw(c101.143,88.236) pad.0@101.735,87.645 ; pad.0@102.33,87.15 cw(c102.933,86.546) 102.933,87.4 ; pad.0@102.33,87.645 ccw(c102.921,88.236) 102.921,87.4 ; 107.398,87.57 cw(c107.398,85.656) pad.0@108.751,87.009 ; 107.544,87.57 ccw(c107.544,89.277) pad.0@108.751,88.07 ; 108.123,87.57 cw(c108.123,86.38) pad.0@108.964,87.221 ; 108.268,87.57 ccw(c108.268,88.553) pad.0@108.964,87.858 ; pad.0@109.6,87.221 cw(c110.441,86.38) 110.441,87.57 ; pad.0@109.6,87.858 ccw(c110.295,88.553) 110.295,87.57 ; pad.0@109.812,87.009 cw(c111.165,85.656) pad.0@111.165,87.57 ; pad.0@109.812,88.07 ccw(c111.02,89.277) pad.0@111.02,87.57 ; pad.0@109.938,87.57 cw(c109.938,85.656) pad.0@111.291,87.009 ; pad.0@110.084,87.57 ccw(c110.084,89.277) pad.0@111.291,88.07 ; 110.663,87.57 cw(c110.663,86.38) pad.0@111.504,87.221 ; 110.808,87.57 ccw(c110.808,88.553) pad.0@111.504,87.858 ; 110.888,87.605 ccw(c111.027,88.123) pad.0@111.459,87.806 ; pad.0@111.161,87.894 cw(c110.284,88.363) 110.541,87.403 cw(c110.691,86.845) pad.0@111.183,87.147 ; pad.0@111.168,87.172 ccw(c110.167,86.61) 110.464,87.718 ccw(c110.647,88.401) pad.0@111.217,87.983
  Bottom w0.3: pad.0@109.291,87.57 pad.0@111.831,87.57 ; pad.0@109.6,87.221 cw(c110.441,86.38) 110.441,87.57 ; pad.0@109.6,87.858 ccw(c110.295,88.553) 110.295,87.57 ; pad.0@109.812,87.009 cw(c111.165,85.656) pad.0@111.165,87.57 ; pad.0@109.812,88.07 ccw(c111.02,89.277) pad.0@111.02,87.57 ; pad.0@109.938,87.57 cw(c109.938,85.656) pad.0@111.291,87.009 ; pad.0@110.084,87.57 ccw(c110.084,89.277) pad.0@111.291,88.07 ; 110.663,87.57 cw(c110.663,86.38) pad.0@111.504,87.221 ; 110.808,87.57 ccw(c110.808,88.553) pad.0@111.504,87.858 ; 110.888,87.605 ccw(c111.027,88.123) pad.0@111.459,87.806 ; pad.0@111.161,87.894 cw(c110.284,88.363) 110.541,87.403 cw(c110.691,86.845) pad.0@111.183,87.147 ; pad.0@111.168,87.172 ccw(c110.167,86.61) 110.464,87.718 ccw(c110.647,88.401) pad.0@111.217,87.983
PA26: pad.0@102.032,86.127 pad.0@109.282,85 pad.0@111.822,85 U1.W13 | length 49.4
  Top w0.3: U1.W13@99.551,86.135 105.266,86.135 106.371,85.03 pad.0@111.831,85.03 ; U1.W13@99.992,86.175 ccw(c100.089,86.273) U1.W13@100.089,86.135 ; U1.W13@100.204,86.387 ccw(c100.813,86.997) U1.W13@100.813,86.135 ; 101.119,86.135 cw(c101.119,85.264) pad.0@101.735,85.88 ; 101.155,86.135 ccw(c101.155,86.954) pad.0@101.735,86.375 ; pad.0@102.33,85.88 cw(c102.945,85.264) 102.945,86.135 ; pad.0@102.33,86.375 ccw(c102.909,86.954) 102.909,86.135 ; 107.398,85.03 cw(c107.398,83.116) pad.0@108.751,84.469 ; 107.544,85.03 ccw(c107.544,86.737) pad.0@108.751,85.53 ; 108.123,85.03 cw(c108.123,83.84) pad.0@108.964,84.681 ; 108.268,85.03 ccw(c108.268,86.013) pad.0@108.964,85.318 ; pad.0@109.6,84.681 cw(c110.441,83.84) 110.441,85.03 ; pad.0@109.6,85.318 ccw(c110.295,86.013) 110.295,85.03 ; pad.0@109.812,84.469 cw(c111.165,83.116) pad.0@111.165,85.03 ; pad.0@109.812,85.53 ccw(c111.02,86.737) pad.0@111.02,85.03 ; pad.0@109.938,85.03 cw(c109.938,83.116) pad.0@111.291,84.469 ; pad.0@110.084,85.03 ccw(c110.084,86.737) pad.0@111.291,85.53 ; 110.663,85.03 cw(c110.663,83.84) pad.0@111.504,84.681 ; 110.808,85.03 ccw(c110.808,86.013) pad.0@111.504,85.318 ; 110.888,85.065 ccw(c111.027,85.583) pad.0@111.459,85.266 ; pad.0@111.161,85.354 cw(c110.284,85.823) 110.541,84.863 cw(c110.691,84.305) pad.0@111.183,84.607 ; pad.0@111.168,84.632 ccw(c110.167,84.07) 110.464,85.178 ccw(c110.647,85.861) pad.0@111.217,85.443
  Bottom w0.3: pad.0@109.291,85.03 pad.0@111.831,85.03 ; pad.0@109.6,84.681 cw(c110.441,83.84) 110.441,85.03 ; pad.0@109.6,85.318 ccw(c110.295,86.013) 110.295,85.03 ; pad.0@109.812,84.469 cw(c111.165,83.116) pad.0@111.165,85.03 ; pad.0@109.812,85.53 ccw(c111.02,86.737) pad.0@111.02,85.03 ; pad.0@109.938,85.03 cw(c109.938,83.116) pad.0@111.291,84.469 ; pad.0@110.084,85.03 ccw(c110.084,86.737) pad.0@111.291,85.53 ; 110.663,85.03 cw(c110.663,83.84) pad.0@111.504,84.681 ; 110.808,85.03 ccw(c110.808,86.013) pad.0@111.504,85.318 ; 110.888,85.065 ccw(c111.027,85.583) pad.0@111.459,85.266 ; pad.0@111.161,85.354 cw(c110.284,85.823) 110.541,84.863 cw(c110.691,84.305) pad.0@111.183,84.607 ; pad.0@111.168,84.632 ccw(c110.167,84.07) 110.464,85.178 ccw(c110.647,85.861) pad.0@111.217,85.443
PA27: pad.0@102.032,84.855 pad.0@109.282,82.46 pad.0@111.822,82.46 U1.W14 | length 49.9
  Top w0.3: U1.W14@99.551,84.865 104.856,84.865 107.231,82.49 pad.0@111.831,82.49 ; U1.W14@99.992,84.905 ccw(c100.089,85.003) U1.W14@100.089,84.865 ; U1.W14@100.204,85.117 ccw(c100.813,85.727) U1.W14@100.813,84.865 ; 101.113,84.865 cw(c101.113,83.986) pad.0@101.735,84.607 ; 101.161,84.865 ccw(c101.161,85.676) pad.0@101.735,85.102 ; pad.0@102.33,84.607 cw(c102.951,83.986) 102.951,84.865 ; pad.0@102.33,85.102 ccw(c102.903,85.676) 102.903,84.865 ; 107.398,82.49 cw(c107.398,80.576) pad.0@108.751,81.929 ; 107.544,82.49 ccw(c107.544,84.197) pad.0@108.751,82.99 ; 108.123,82.49 cw(c108.123,81.3) pad.0@108.964,82.141 ; 108.268,82.49 ccw(c108.268,83.473) pad.0@108.964,82.778 ; pad.0@109.6,82.141 cw(c110.441,81.3) 110.441,82.49 ; pad.0@109.6,82.778 ccw(c110.295,83.473) 110.295,82.49 ; pad.0@109.812,81.929 cw(c111.165,80.576) pad.0@111.165,82.49 ; pad.0@109.812,82.99 ccw(c111.02,84.197) pad.0@111.02,82.49 ; pad.0@109.938,82.49 cw(c109.938,80.576) pad.0@111.291,81.929 ; pad.0@110.084,82.49 ccw(c110.084,84.197) pad.0@111.291,82.99 ; 110.663,82.49 cw(c110.663,81.3) pad.0@111.504,82.141 ; 110.808,82.49 ccw(c110.808,83.473) pad.0@111.504,82.778 ; 110.888,82.525 ccw(c111.027,83.043) pad.0@111.459,82.726 ; pad.0@111.161,82.814 cw(c110.284,83.283) 110.541,82.323 cw(c110.691,81.765) pad.0@111.183,82.067 ; pad.0@111.168,82.092 ccw(c110.167,81.53) 110.464,82.638 ccw(c110.647,83.321) pad.0@111.217,82.903
  Bottom w0.3: pad.0@109.291,82.49 pad.0@111.831,82.49 ; pad.0@109.6,82.141 cw(c110.441,81.3) 110.441,82.49 ; pad.0@109.6,82.778 ccw(c110.295,83.473) 110.295,82.49 ; pad.0@109.812,81.929 cw(c111.165,80.576) pad.0@111.165,82.49 ; pad.0@109.812,82.99 ccw(c111.02,84.197) pad.0@111.02,82.49 ; pad.0@109.938,82.49 cw(c109.938,80.576) pad.0@111.291,81.929 ; pad.0@110.084,82.49 ccw(c110.084,84.197) pad.0@111.291,82.99 ; 110.663,82.49 cw(c110.663,81.3) pad.0@111.504,82.141 ; 110.808,82.49 ccw(c110.808,83.473) pad.0@111.504,82.778 ; 110.888,82.525 ccw(c111.027,83.043) pad.0@111.459,82.726 ; pad.0@111.161,82.814 cw(c110.284,83.283) 110.541,82.323 cw(c110.691,81.765) pad.0@111.183,82.067 ; pad.0@111.168,82.092 ccw(c110.167,81.53) 110.464,82.638 ccw(c110.647,83.321) pad.0@111.217,82.903
PA28: pad.0@102.032,83.587 pad.0@109.282,79.92 pad.0@111.822,79.92 U1.W15 | length 47
  Top w0.3: U1.W15@99.551,83.595 104.526,83.595 108.171,79.95 ; U1.W15@99.992,83.635 ccw(c100.089,83.733) U1.W15@100.089,83.595 ; U1.W15@100.204,83.847 ccw(c100.813,84.457) U1.W15@100.813,83.595 ; 101.119,83.595 cw(c101.119,82.724) pad.0@101.735,83.34 ; 101.155,83.595 ccw(c101.155,84.414) pad.0@101.735,83.835 ; pad.0@102.33,83.34 cw(c102.945,82.724) 102.945,83.595 ; pad.0@102.33,83.835 ccw(c102.909,84.414) 102.909,83.595 ; pad.0@108.576,79.665 ccw(c108.171,79.519) 108.171,79.95 ; pad.0@108.597,80.226 cw(c108.171,80.416) 108.171,79.95 ; pad.0@109.6,79.601 cw(c110.441,78.76) 110.441,79.95 ; pad.0@109.6,80.238 ccw(c110.295,80.933) 110.295,79.95 ; pad.0@109.812,79.389 cw(c111.165,78.036) pad.0@111.165,79.95 ; pad.0@109.812,80.45 ccw(c111.02,81.657) pad.0@111.02,79.95 ; pad.0@109.938,79.95 cw(c109.938,78.036) pad.0@111.291,79.389 ; pad.0@110.084,79.95 ccw(c110.084,81.657) pad.0@111.291,80.45 ; 110.663,79.95 cw(c110.663,78.76) pad.0@111.504,79.601 ; 110.808,79.95 ccw(c110.808,80.933) pad.0@111.504,80.238 ; 110.888,79.985 ccw(c111.027,80.503) pad.0@111.459,80.186 ; pad.0@111.161,80.274 cw(c110.284,80.743) 110.541,79.783 cw(c110.691,79.225) pad.0@111.183,79.527 ; pad.0@111.168,79.552 ccw(c110.167,78.99) 110.464,80.098 ccw(c110.647,80.781) pad.0@111.217,80.363 ; pad.0@111.831,79.95 108.171,79.95
  Bottom w0.3: pad.0@109.291,79.95 pad.0@111.831,79.95 ; pad.0@109.6,79.601 cw(c110.441,78.76) 110.441,79.95 ; pad.0@109.6,80.238 ccw(c110.295,80.933) 110.295,79.95 ; pad.0@109.812,79.389 cw(c111.165,78.036) pad.0@111.165,79.95 ; pad.0@109.812,80.45 ccw(c111.02,81.657) pad.0@111.02,79.95 ; pad.0@109.938,79.95 cw(c109.938,78.036) pad.0@111.291,79.389 ; pad.0@110.084,79.95 ccw(c110.084,81.657) pad.0@111.291,80.45 ; 110.663,79.95 cw(c110.663,78.76) pad.0@111.504,79.601 ; 110.808,79.95 ccw(c110.808,80.933) pad.0@111.504,80.238 ; 110.888,79.985 ccw(c111.027,80.503) pad.0@111.459,80.186 ; pad.0@111.161,80.274 cw(c110.284,80.743) 110.541,79.783 cw(c110.691,79.225) pad.0@111.183,79.527 ; pad.0@111.168,79.552 ccw(c110.167,78.99) 110.464,80.098 ccw(c110.647,80.781) pad.0@111.217,80.363
PA29: pad.0@102.032,82.317 pad.0@109.282,77.38 pad.0@111.822,77.38 U1.W16 | length 51
  Top w0.3: U1.W16@99.551,82.325 104.376,82.325 109.291,77.41 pad.0@111.831,77.41 ; U1.W16@99.992,82.365 ccw(c100.089,82.463) U1.W16@100.089,82.325 ; U1.W16@100.204,82.577 ccw(c100.813,83.187) U1.W16@100.813,82.325 ; 101.119,82.325 cw(c101.119,81.454) pad.0@101.735,82.07 ; 101.155,82.325 ccw(c101.155,83.144) pad.0@101.735,82.565 ; pad.0@102.33,82.07 cw(c102.945,81.454) 102.945,82.325 ; pad.0@102.33,82.565 ccw(c102.909,83.144) 102.909,82.325 ; 107.973,78.727 cw(c106.626,77.38) pad.0@108.532,77.38 ; 108.069,78.632 ccw(c109.282,79.845) pad.0@109.282,78.13 ; pad.0@108.486,78.215 cw(c107.65,77.38) pad.0@108.832,77.38 ; pad.0@108.581,78.12 ccw(c109.282,78.82) pad.0@109.282,77.83 ; pad.0@109.6,77.061 cw(c110.441,76.22) 110.441,77.41 ; pad.0@109.6,77.698 ccw(c110.295,78.393) 110.295,77.41 ; pad.0@109.812,76.849 cw(c111.165,75.496) pad.0@111.165,77.41 ; pad.0@109.812,77.91 ccw(c111.02,79.117) pad.0@111.02,77.41 ; pad.0@109.938,77.41 cw(c109.938,75.496) pad.0@111.291,76.849 ; pad.0@110.084,77.41 ccw(c110.084,79.117) pad.0@111.291,77.91 ; 110.663,77.41 cw(c110.663,76.22) pad.0@111.504,77.061 ; 110.808,77.41 ccw(c110.808,78.393) pad.0@111.504,77.698 ; 110.888,77.445 ccw(c111.027,77.963) pad.0@111.459,77.646 ; pad.0@111.161,77.734 cw(c110.284,78.203) 110.541,77.243 cw(c110.691,76.685) pad.0@111.183,76.987 ; pad.0@111.168,77.012 ccw(c110.167,76.45) 110.464,77.558 ccw(c110.647,78.241) pad.0@111.217,77.823
  Bottom w0.3: pad.0@109.291,77.41 pad.0@111.831,77.41 ; pad.0@109.6,77.061 cw(c110.441,76.22) 110.441,77.41 ; pad.0@109.6,77.698 ccw(c110.295,78.393) 110.295,77.41 ; pad.0@109.812,76.849 cw(c111.165,75.496) pad.0@111.165,77.41 ; pad.0@109.812,77.91 ccw(c111.02,79.117) pad.0@111.02,77.41 ; pad.0@109.938,77.41 cw(c109.938,75.496) pad.0@111.291,76.849 ; pad.0@110.084,77.41 ccw(c110.084,79.117) pad.0@111.291,77.91 ; 110.663,77.41 cw(c110.663,76.22) pad.0@111.504,77.061 ; 110.808,77.41 ccw(c110.808,78.393) pad.0@111.504,77.698 ; 110.888,77.445 ccw(c111.027,77.963) pad.0@111.459,77.646 ; pad.0@111.161,77.734 cw(c110.284,78.203) 110.541,77.243 cw(c110.691,76.685) pad.0@111.183,76.987 ; pad.0@111.168,77.012 ccw(c110.167,76.45) 110.464,77.558 ccw(c110.647,78.241) pad.0@111.217,77.823
PA30: "LCD Display.6" pad.0@102.032,81.047 pad.0@109.282,74.84 pad.0@111.822,74.84 pad.0@121.982,123.1 pad.0@131.711,129.853 U1.W17 | length 137
  Top w0.3: 101.264,81.1 ccw(c101.264,81.765) pad.0@101.735,81.295 ; pad.0@101.718,80.818 ccw(c101.101,80.283) 101.101,81.1 104.481,81.1 107.901,77.68 107.901,76.14 109.171,74.87 pad.0@111.831,74.87 ; pad.0@102.33,80.8 cw(c103.054,80.076) 103.054,81.1 ; pad.0@102.33,81.295 ccw(c102.8,81.765) 102.8,81.1 ; pad.0@109.6,74.521 cw(c110.441,73.68) 110.441,74.87 ; pad.0@109.6,75.158 ccw(c110.295,75.853) 110.295,74.87 ; pad.0@109.812,74.309 cw(c111.165,72.956) pad.0@111.165,74.87 ; pad.0@109.812,75.37 ccw(c111.02,76.577) pad.0@111.02,74.87 ; pad.0@109.938,74.87 cw(c109.938,72.956) pad.0@111.291,74.309 ; pad.0@110.084,74.87 ccw(c110.084,76.577) pad.0@111.291,75.37 ; 110.663,74.87 cw(c110.663,73.68) pad.0@111.504,74.521 ; 110.808,74.87 ccw(c110.808,75.853) pad.0@111.504,75.158 ; 110.888,74.905 ccw(c111.027,75.423) pad.0@111.459,75.106 ; pad.0@111.161,75.194 cw(c110.284,75.663) 110.541,74.703 cw(c110.691,74.145) pad.0@111.183,74.447 ; pad.0@111.168,74.472 ccw(c110.167,73.91) 110.464,75.018 ccw(c110.647,75.701) pad.0@111.217,75.283 ; pad.0@121.451,123.63 ccw(c119.907,125.174) 122.091,125.174 ; pad.0@121.664,123.418 ccw(c120.631,124.45) 122.091,124.45 ; pad.0@122.061,123.18 122.091,123.21 122.091,127.19 123.58,128.679 131.42,128.679 131.718,128.976 131.718,131.561 ; 122.091,124.646 ccw(c123.528,124.646) pad.0@122.512,123.63 ; 131.47,131.014 cw(c130.873,130.416) 131.718,130.416 cw(c132.563,130.416) 131.965,131.014 ; pad.0@131.534,129.526 cw(c131.092,129.083) 131.718,129.083 ; pad.0@131.534,130.179 ccw(c131.092,130.622) 131.718,130.622 ; 131.718,129.115 cw(c132.299,129.115) pad.0@131.888,129.526 ; 131.718,130.59 ccw(c132.299,130.59) pad.0@131.888,130.179
  Bottom w0.3: pad.0@109.291,74.87 111.831,74.87 113.371,74.87 ; pad.0@109.6,74.521 cw(c110.441,73.68) 110.441,74.87 ; pad.0@109.6,75.158 ccw(c110.295,75.853) 110.295,74.87 ; pad.0@109.812,74.309 cw(c111.165,72.956) pad.0@111.165,74.87 ; pad.0@109.812,75.37 ccw(c111.02,76.577) pad.0@111.02,74.87 ; pad.0@109.938,74.87 cw(c109.938,72.956) pad.0@111.291,74.309 ; pad.0@110.084,74.87 ccw(c110.084,76.577) pad.0@111.291,75.37 ; 110.663,74.87 cw(c110.663,73.68) pad.0@111.504,74.521 ; 110.808,74.87 ccw(c110.808,75.853) pad.0@111.504,75.158 ; 110.888,74.905 ccw(c111.027,75.423) pad.0@111.459,75.106 ; pad.0@111.161,75.194 cw(c110.284,75.663) 110.541,74.703 cw(c110.691,74.145) pad.0@111.183,74.447 ; pad.0@111.168,74.472 ccw(c110.167,73.91) 110.464,75.018 ccw(c110.647,75.701) pad.0@111.217,75.283 ; pad.0@112.166,75.13 ccw(c112.725,75.602) 112.725,74.87 ; pad.0@112.183,74.572 cw(c112.775,74.133) 112.775,74.87 ; pad.0@112.395,75.323 ccw(c113.371,76.147) 113.371,74.87 ; pad.0@112.424,74.393 cw(c113.371,73.691) 113.371,74.87 ; 120.026,123.16 cw(c120.026,121.144) pad.0@121.451,122.569 ; 120.316,123.16 ccw(c120.316,124.765) pad.0@121.451,123.63 ; 120.75,123.16 cw(c120.75,121.868) pad.0@121.664,122.781 ; 121.04,123.16 ccw(c121.04,124.041) pad.0@121.664,123.418 ; pad.0@122.091,123.16 119.446,123.16 116.921,120.635 116.921,100.39 116.106,99.574 116.106,98.215 116.921,97.4 116.921,78.42 113.371,74.87 ; 131.47,131.014 cw(c130.873,130.416) 131.718,130.416 cw(c132.563,130.416) 131.965,131.014 ; pad.0@131.534,130.179 ccw(c131.092,130.622) 131.718,130.622 ; pad.0@131.711,130.16 131.718,130.203 131.718,131.561 ; 131.718,130.59 ccw(c132.299,130.59) pad.0@131.888,130.179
